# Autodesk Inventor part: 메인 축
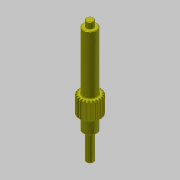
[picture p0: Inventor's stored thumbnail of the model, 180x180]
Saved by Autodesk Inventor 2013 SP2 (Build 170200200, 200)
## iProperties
Created: 2016-02
Part Number: 메인 축
Material: 강철, 연강
Document SubType Name: Modeling
Categories: <?xml version="1.0" encoding="UTF-16"?> <MemberInstance><Categories><FamilyTemplate><FamilyTemplateParameter ValueType="xs:double" Id="1" ObjectReferenceKey="da
Density: 7.86 g/cm^3
Mass: 187.503 g
Surface Area: 82.0529 cm^2
Volume: 23.8554 cm^3
Author: mdu
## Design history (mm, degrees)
sketch "Sketch1"
  geometry: C1 r 12 at (0, 0)
  constraints: 1 centre point
  dimensions: "d0" = 24 diameter of C1 (= da_da)
extrude "Extrusion1" new body sketch "Sketch1" distance "d1" = 20 (= da_b); taper "d2" = 0 deg
workplane "Work Plane2"
feature "피치 지름" dims "d4" = 10, "d5" = 0
workplane "Work Plane8"
workplane "Work Plane9"
chamfer "모따기1" distance "d49" = 1; stored, may be unused: second distance "d50" = 2, angle "d51" = 45 deg
sketch "스케치3"
  geometry: C1 r 7.5 at (0, 0); 1 further point
  constraints: 1 centre point, 1 coincident
  dimensions: "d52" = 15 diameter of C1
extrude "돌출2" join sketch "스케치3" distance "d53" = 66; taper "d54" = 0 deg
sketch "스케치4"
  geometry: C1 r 4 at (0, 0); 1 further point
  constraints: 1 centre point, 1 coincident
  dimensions: "d55" = 8 diameter of C1
extrude "돌출3" join sketch "스케치4" distance "d56" = 7; taper "d57" = 0 deg
sketch "스케치5"
  geometry: C1 r 7.5 at (0, 0) reference; C2 r 7.5 at (0, 0) reference; 1 further point
extrude "돌출4" join sketch "스케치5" distance "d62" = 16; taper "d63" = 0 deg
sketch "스케치6"
  geometry: C1 r 4 at (0, 0); 1 further point
  constraints: 1 centre point, 1 coincident
  dimensions: "d64" = 8 diameter of C1
extrude "돌출5" join sketch "스케치6" distance "d65" = 30; taper "d66" = 0 deg
chamfer "모따기2" distance "d58" = 0.5; stored, may be unused: second distance "d59" = 2, angle "d60" = 45 deg
fillet "모깎기1" dims "d61" = 0.5
feature "스퍼 기어" dims "da_b" = 20, "da_d" = 22, "da_aw" = 31, "da_da" = 24, "da_df" = 19.5, "da_dw" = 22, angle "da_beta" = 0 deg, "da_lefttooth" = 0, "da_righttooth" = 0
sketch "스케치7" dims "d68" = 18
  geometry: C1 r 0.25 at (0, -9); 2 further points
  constraints: 2 vertical alignment, 1 centre point, 1 coincident, 2 other
  dimensions: "d67" = 0.5 diameter of C1
extrude "돌출6" join sketch "스케치7" distance "d69" = 0.3; taper "d70" = 0 deg
body "Solid1"
sketch "Sketch2"
  geometry: C1 r 12 at (0, 0) reference; C2 r 11 at (0, 0)
  constraints: 1 centre point, 1 coincident
  dimensions: "d3" = 22 diameter of C2 (= da_dw)
body "Srf1"
node "투영된 루프1"
other parameters: "d16" = 31 (= da_aw), "d17" = 0, "d34" = 1.428 (computed from da_z), "d39" = 0, "d41" = 0, "d43" = 31 (= da_aw), "d46" = 31 (= da_aw), "d47" = 0, "d48" = 0
